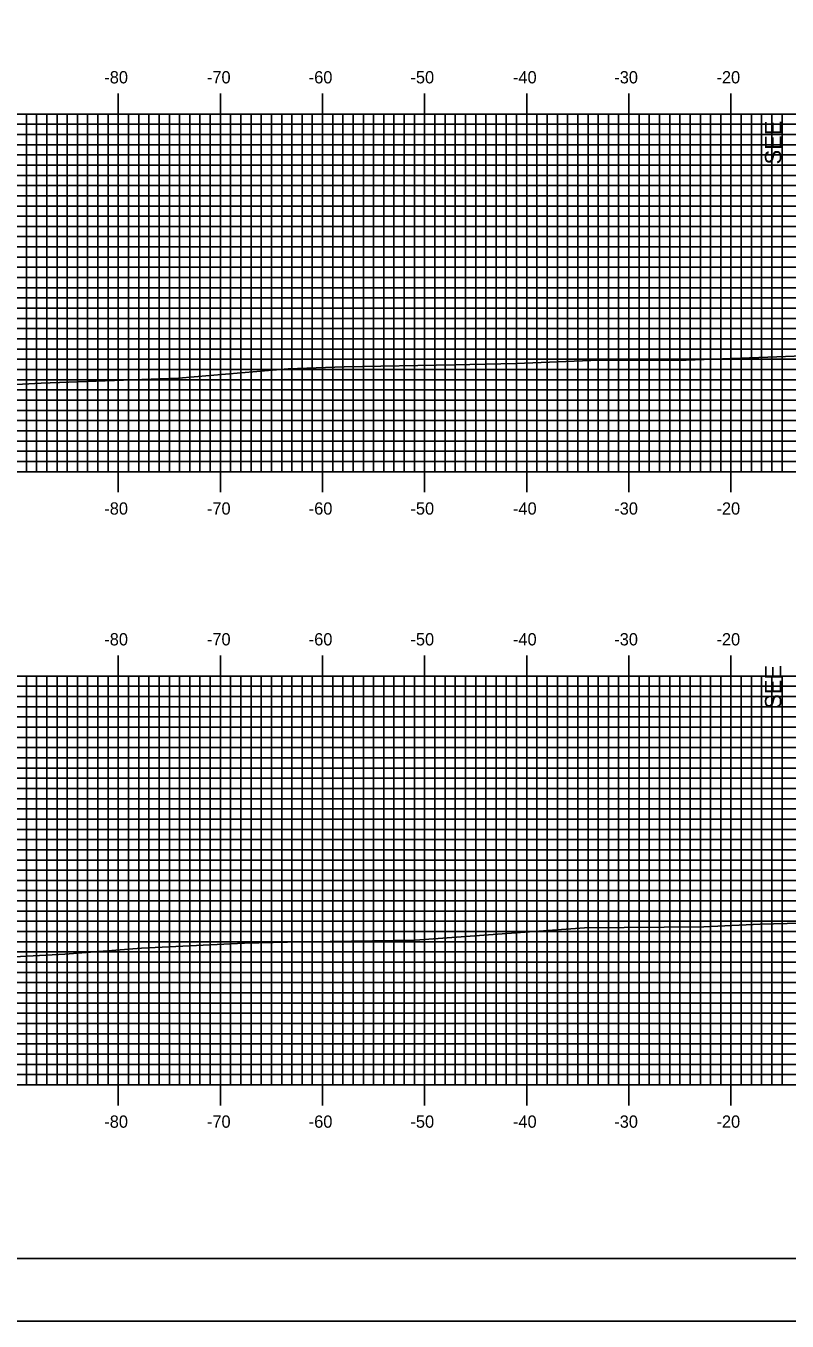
# Model space of a CAD drawing. Extents: x 879 to 1222, y -1658 to -1438.
# Drawn here: x 955.6 to 1030.1, y -1657.7 to -1531 of the extents above; entities that cross this region are included whole.
import ezdxf

# ---------------------------------------------------------------- set-up
doc = ezdxf.new("R2010")
doc.units = 0
for name, color, linetype in [('ANNOTATION', 7, 'Continuous'), ('BORDER', 7, 'Continuous'), ('H_V ANNOTATION', 7, 'Continuous'), ('MAJOR', 7, 'Continuous'), ('MINOR', 7, 'Continuous'), ('PLOT BOUNDARY', 7, 'Continuous'), ('S_Roadway_Centerline', 7, 'Continuous')]:
    doc.layers.add(name, color=color, linetype=linetype)

msp = doc.modelspace()

# ---------------------------------------------------------------- linework, layer by layer
at = {"layer": 'BORDER'}
msp.add_lwpolyline([(895.05, -1651.6), (1215.05, -1651.6), (1215.05, -1441.6), (895.05, -1441.6)], close=True, dxfattribs=at)
at = {"layer": 'MAJOR'}
for p, q in [((964.65, -1537.6), (964.65, -1539.6)), ((974.65, -1537.6), (974.65, -1539.6)), ((984.65, -1537.6), (984.65, -1539.6)), ((994.65, -1537.6), (994.65, -1539.6)), ((1004.65, -1537.6), (1004.65, -1539.6)), ((1014.65, -1537.6), (1014.65, -1539.6)), ((1024.65, -1537.6), (1024.65, -1539.6)), ((904.65, -1539.6), (1184.65, -1539.6)), ((904.65, -1539.6), (1184.65, -1539.6)), ((964.65, -1574.6), (964.65, -1539.6)), ((974.65, -1574.6), (974.65, -1539.6)), ((984.65, -1574.6), (984.65, -1539.6)), ((994.65, -1574.6), (994.65, -1539.6)), ((1004.65, -1574.6), (1004.65, -1539.6)), ((1014.65, -1574.6), (1014.65, -1539.6)), ((1024.65, -1574.6), (1024.65, -1539.6)), ((904.65, -1544.6), (1184.65, -1544.6)), ((904.65, -1549.6), (1184.65, -1549.6)), ((904.65, -1554.6), (1184.65, -1554.6)), ((904.65, -1559.6), (1184.65, -1559.6)), ((904.65, -1564.6), (1184.65, -1564.6)), ((904.65, -1569.6), (1184.65, -1569.6)), ((904.65, -1574.6), (1184.65, -1574.6)), ((904.65, -1574.6), (1184.65, -1574.6)), ((964.65, -1576.61), (964.65, -1574.6)), ((974.65, -1576.61), (974.65, -1574.6)), ((984.65, -1576.61), (984.65, -1574.6)), ((994.65, -1576.61), (994.65, -1574.6)), ((1004.65, -1576.61), (1004.65, -1574.6)), ((1014.65, -1576.61), (1014.65, -1574.6)), ((1024.65, -1576.61), (1024.65, -1574.6)), ((964.65, -1592.6), (964.65, -1594.6)), ((974.65, -1592.6), (974.65, -1594.6)), ((984.65, -1592.6), (984.65, -1594.6)), ((994.65, -1592.6), (994.65, -1594.6)), ((1004.65, -1592.6), (1004.65, -1594.6)), ((1014.65, -1592.6), (1014.65, -1594.6)), ((1024.65, -1592.6), (1024.65, -1594.6)), ((904.65, -1594.6), (1184.65, -1594.6)), ((904.65, -1594.6), (1184.65, -1594.6)), ((964.65, -1634.6), (964.65, -1594.6)), ((974.65, -1634.6), (974.65, -1594.6)), ((984.65, -1634.6), (984.65, -1594.6)), ((994.65, -1634.6), (994.65, -1594.6)), ((1004.65, -1634.6), (1004.65, -1594.6)), ((1014.65, -1634.6), (1014.65, -1594.6)), ((1024.65, -1634.6), (1024.65, -1594.6)), ((904.65, -1599.6), (1184.65, -1599.6)), ((904.65, -1604.6), (1184.65, -1604.6)), ((904.65, -1609.6), (1184.65, -1609.6)), ((904.65, -1614.6), (1184.65, -1614.6)), ((904.65, -1619.6), (1184.65, -1619.6)), ((904.65, -1624.6), (1184.65, -1624.6)), ((904.65, -1629.6), (1184.65, -1629.6)), ((904.65, -1634.6), (1184.65, -1634.6)), ((904.65, -1634.6), (1184.65, -1634.6)), ((964.65, -1636.61), (964.65, -1634.6)), ((974.65, -1636.61), (974.65, -1634.6)), ((984.65, -1636.61), (984.65, -1634.6)), ((994.65, -1636.61), (994.65, -1634.6)), ((1004.65, -1636.61), (1004.65, -1634.6)), ((1014.65, -1636.61), (1014.65, -1634.6)), ((1024.65, -1636.61), (1024.65, -1634.6))]:
    msp.add_line(p, q, dxfattribs=at)
at = {"layer": 'MINOR'}
for p, q in [((955.65, -1574.6), (955.65, -1539.6)), ((956.65, -1574.6), (956.65, -1539.6)), ((957.65, -1574.6), (957.65, -1539.6)), ((958.65, -1574.6), (958.65, -1539.6)), ((959.65, -1574.6), (959.65, -1539.6)), ((960.65, -1574.6), (960.65, -1539.6)), ((961.65, -1574.6), (961.65, -1539.6)), ((962.65, -1574.6), (962.65, -1539.6)), ((963.65, -1574.6), (963.65, -1539.6)), ((965.65, -1574.6), (965.65, -1539.6)), ((966.65, -1574.6), (966.65, -1539.6)), ((967.65, -1574.6), (967.65, -1539.6)), ((968.65, -1574.6), (968.65, -1539.6)), ((969.65, -1574.6), (969.65, -1539.6)), ((970.65, -1574.6), (970.65, -1539.6)), ((971.65, -1574.6), (971.65, -1539.6)), ((972.65, -1574.6), (972.65, -1539.6)), ((973.65, -1574.6), (973.65, -1539.6)), ((975.65, -1574.6), (975.65, -1539.6)), ((976.65, -1574.6), (976.65, -1539.6)), ((977.65, -1574.6), (977.65, -1539.6)), ((978.65, -1574.6), (978.65, -1539.6)), ((979.65, -1574.6), (979.65, -1539.6)), ((980.65, -1574.6), (980.65, -1539.6)), ((981.65, -1574.6), (981.65, -1539.6)), ((982.65, -1574.6), (982.65, -1539.6)), ((983.65, -1574.6), (983.65, -1539.6)), ((985.65, -1574.6), (985.65, -1539.6)), ((986.65, -1574.6), (986.65, -1539.6)), ((987.65, -1574.6), (987.65, -1539.6)), ((988.65, -1574.6), (988.65, -1539.6)), ((989.65, -1574.6), (989.65, -1539.6)), ((990.65, -1574.6), (990.65, -1539.6)), ((991.65, -1574.6), (991.65, -1539.6)), ((992.65, -1574.6), (992.65, -1539.6)), ((993.65, -1574.6), (993.65, -1539.6)), ((995.65, -1574.6), (995.65, -1539.6)), ((996.65, -1574.6), (996.65, -1539.6)), ((997.65, -1574.6), (997.65, -1539.6)), ((998.65, -1574.6), (998.65, -1539.6)), ((999.65, -1574.6), (999.65, -1539.6)), ((1000.65, -1574.6), (1000.65, -1539.6)), ((1001.65, -1574.6), (1001.65, -1539.6)), ((1002.65, -1574.6), (1002.65, -1539.6)), ((1003.65, -1574.6), (1003.65, -1539.6)), ((1005.65, -1574.6), (1005.65, -1539.6)), ((1006.65, -1574.6), (1006.65, -1539.6)), ((1007.65, -1574.6), (1007.65, -1539.6)), ((1008.65, -1574.6), (1008.65, -1539.6)), ((1009.65, -1574.6), (1009.65, -1539.6)), ((1010.65, -1574.6), (1010.65, -1539.6)), ((1011.65, -1574.6), (1011.65, -1539.6)), ((1012.65, -1574.6), (1012.65, -1539.6)), ((1013.65, -1574.6), (1013.65, -1539.6)), ((1015.65, -1574.6), (1015.65, -1539.6)), ((1016.65, -1574.6), (1016.65, -1539.6)), ((1017.65, -1574.6), (1017.65, -1539.6)), ((1018.65, -1574.6), (1018.65, -1539.6)), ((1019.65, -1574.6), (1019.65, -1539.6)), ((1020.65, -1574.6), (1020.65, -1539.6)), ((1021.65, -1574.6), (1021.65, -1539.6)), ((1022.65, -1574.6), (1022.65, -1539.6)), ((1023.65, -1574.6), (1023.65, -1539.6)), ((1025.65, -1574.6), (1025.65, -1539.6)), ((1026.65, -1574.6), (1026.65, -1539.6)), ((1027.65, -1574.6), (1027.65, -1539.6)), ((1028.65, -1574.6), (1028.65, -1539.6)), ((1029.65, -1574.6), (1029.65, -1539.6)), ((904.65, -1540.6), (1184.65, -1540.6)), ((904.65, -1541.6), (1184.65, -1541.6)), ((904.65, -1542.6), (1184.65, -1542.6)), ((904.65, -1543.6), (1184.65, -1543.6)), ((904.65, -1545.6), (1184.65, -1545.6)), ((904.65, -1546.6), (1184.65, -1546.6)), ((904.65, -1547.6), (1184.65, -1547.6)), ((904.65, -1548.6), (1184.65, -1548.6)), ((904.65, -1550.6), (1184.65, -1550.6)), ((904.65, -1551.6), (1184.65, -1551.6)), ((904.65, -1552.6), (1184.65, -1552.6)), ((904.65, -1553.6), (1184.65, -1553.6)), ((904.65, -1555.6), (1184.65, -1555.6)), ((904.65, -1556.6), (1184.65, -1556.6)), ((904.65, -1557.6), (1184.65, -1557.6)), ((904.65, -1558.6), (1184.65, -1558.6)), ((904.65, -1560.6), (1184.65, -1560.6)), ((904.65, -1561.6), (1184.65, -1561.6)), ((904.65, -1562.6), (1184.65, -1562.6)), ((904.65, -1563.6), (1184.65, -1563.6)), ((904.65, -1565.6), (1184.65, -1565.6)), ((904.65, -1566.6), (1184.65, -1566.6)), ((904.65, -1567.6), (1184.65, -1567.6)), ((904.65, -1568.6), (1184.65, -1568.6)), ((904.65, -1570.6), (1184.65, -1570.6)), ((904.65, -1571.6), (1184.65, -1571.6)), ((904.65, -1572.6), (1184.65, -1572.6)), ((904.65, -1573.6), (1184.65, -1573.6)), ((904.65, -1595.6), (1184.65, -1595.6)), ((955.65, -1634.6), (955.65, -1594.6)), ((956.65, -1634.6), (956.65, -1594.6)), ((957.65, -1634.6), (957.65, -1594.6)), ((958.65, -1634.6), (958.65, -1594.6)), ((959.65, -1634.6), (959.65, -1594.6)), ((960.65, -1634.6), (960.65, -1594.6)), ((961.65, -1634.6), (961.65, -1594.6)), ((962.65, -1634.6), (962.65, -1594.6)), ((963.65, -1634.6), (963.65, -1594.6)), ((965.65, -1634.6), (965.65, -1594.6)), ((966.65, -1634.6), (966.65, -1594.6)), ((967.65, -1634.6), (967.65, -1594.6)), ((968.65, -1634.6), (968.65, -1594.6)), ((969.65, -1634.6), (969.65, -1594.6)), ((970.65, -1634.6), (970.65, -1594.6)), ((971.65, -1634.6), (971.65, -1594.6)), ((972.65, -1634.6), (972.65, -1594.6)), ((973.65, -1634.6), (973.65, -1594.6)), ((975.65, -1634.6), (975.65, -1594.6)), ((976.65, -1634.6), (976.65, -1594.6)), ((977.65, -1634.6), (977.65, -1594.6)), ((978.65, -1634.6), (978.65, -1594.6)), ((979.65, -1634.6), (979.65, -1594.6)), ((980.65, -1634.6), (980.65, -1594.6)), ((981.65, -1634.6), (981.65, -1594.6)), ((982.65, -1634.6), (982.65, -1594.6)), ((983.65, -1634.6), (983.65, -1594.6)), ((985.65, -1634.6), (985.65, -1594.6)), ((986.65, -1634.6), (986.65, -1594.6)), ((987.65, -1634.6), (987.65, -1594.6)), ((988.65, -1634.6), (988.65, -1594.6)), ((989.65, -1634.6), (989.65, -1594.6)), ((990.65, -1634.6), (990.65, -1594.6)), ((991.65, -1634.6), (991.65, -1594.6)), ((992.65, -1634.6), (992.65, -1594.6)), ((993.65, -1634.6), (993.65, -1594.6)), ((995.65, -1634.6), (995.65, -1594.6)), ((996.65, -1634.6), (996.65, -1594.6)), ((997.65, -1634.6), (997.65, -1594.6)), ((998.65, -1634.6), (998.65, -1594.6)), ((999.65, -1634.6), (999.65, -1594.6)), ((1000.65, -1634.6), (1000.65, -1594.6)), ((1001.65, -1634.6), (1001.65, -1594.6)), ((1002.65, -1634.6), (1002.65, -1594.6)), ((1003.65, -1634.6), (1003.65, -1594.6)), ((1005.65, -1634.6), (1005.65, -1594.6)), ((1006.65, -1634.6), (1006.65, -1594.6)), ((1007.65, -1634.6), (1007.65, -1594.6)), ((1008.65, -1634.6), (1008.65, -1594.6)), ((1009.65, -1634.6), (1009.65, -1594.6)), ((1010.65, -1634.6), (1010.65, -1594.6)), ((1011.65, -1634.6), (1011.65, -1594.6)), ((1012.65, -1634.6), (1012.65, -1594.6)), ((1013.65, -1634.6), (1013.65, -1594.6)), ((1015.65, -1634.6), (1015.65, -1594.6)), ((1016.65, -1634.6), (1016.65, -1594.6)), ((1017.65, -1634.6), (1017.65, -1594.6)), ((1018.65, -1634.6), (1018.65, -1594.6)), ((1019.65, -1634.6), (1019.65, -1594.6)), ((1020.65, -1634.6), (1020.65, -1594.6)), ((1021.65, -1634.6), (1021.65, -1594.6)), ((1022.65, -1634.6), (1022.65, -1594.6)), ((1023.65, -1634.6), (1023.65, -1594.6)), ((1025.65, -1634.6), (1025.65, -1594.6)), ((1026.65, -1634.6), (1026.65, -1594.6)), ((1027.65, -1634.6), (1027.65, -1594.6)), ((1028.65, -1634.6), (1028.65, -1594.6)), ((1029.65, -1634.6), (1029.65, -1594.6)), ((904.65, -1596.6), (1184.65, -1596.6)), ((904.65, -1597.6), (1184.65, -1597.6)), ((904.65, -1598.6), (1184.65, -1598.6)), ((904.65, -1600.6), (1184.65, -1600.6)), ((904.65, -1601.6), (1184.65, -1601.6)), ((904.65, -1602.6), (1184.65, -1602.6)), ((904.65, -1603.6), (1184.65, -1603.6)), ((904.65, -1605.6), (1184.65, -1605.6)), ((904.65, -1606.6), (1184.65, -1606.6)), ((904.65, -1607.6), (1184.65, -1607.6)), ((904.65, -1608.6), (1184.65, -1608.6)), ((904.65, -1610.6), (1184.65, -1610.6)), ((904.65, -1611.6), (1184.65, -1611.6)), ((904.65, -1612.6), (1184.65, -1612.6)), ((904.65, -1613.6), (1184.65, -1613.6)), ((904.65, -1615.6), (1184.65, -1615.6)), ((904.65, -1616.6), (1184.65, -1616.6)), ((904.65, -1617.6), (1184.65, -1617.6)), ((904.65, -1618.6), (1184.65, -1618.6)), ((904.65, -1620.6), (1184.65, -1620.6)), ((904.65, -1621.6), (1184.65, -1621.6)), ((904.65, -1622.6), (1184.65, -1622.6)), ((904.65, -1623.6), (1184.65, -1623.6)), ((904.65, -1625.6), (1184.65, -1625.6)), ((904.65, -1626.6), (1184.65, -1626.6)), ((904.65, -1627.6), (1184.65, -1627.6)), ((904.65, -1628.6), (1184.65, -1628.6)), ((904.65, -1630.6), (1184.65, -1630.6)), ((904.65, -1631.6), (1184.65, -1631.6)), ((904.65, -1632.6), (1184.65, -1632.6)), ((904.65, -1633.6), (1184.65, -1633.6))]:
    msp.add_line(p, q, dxfattribs=at)
at = {"layer": 'PLOT BOUNDARY'}
msp.add_lwpolyline([(878.86, -1657.72), (1218.86, -1657.72), (1218.86, -1437.72), (878.86, -1437.72)], close=True, dxfattribs=at)
at = {"layer": 'S_Roadway_Centerline'}
for points in [[(904.65, -1569.39), (906.57, -1569.27), (920.82, -1568), (927.72, -1567.6), (937.47, -1567.07), (938.95, -1567), (940.37, -1566.88), (954.06, -1566.11), (957.1, -1565.94), (970.54, -1565.45), (981.3, -1564.54), (986.76, -1564.33), (997.58, -1564.13), (1003.63, -1564.01), (1010.92, -1563.72), (1020.27, -1563.67), (1029.13, -1563.37), (1035.94, -1563.09)], [(904.65, -1624.72), (905.67, -1624.65), (909.42, -1624.47), (921.92, -1623.77), (925.24, -1623.6), (926.03, -1623.57), (939.03, -1623.13), (942.41, -1622.85), (952.55, -1622.18), (959.41, -1621.83), (966.93, -1621.24), (977.01, -1620.75), (981.23, -1620.64), (993.73, -1620.44), (997.78, -1620.14), (1010.31, -1619.24), (1022, -1619.15), (1027.5, -1618.88), (1036.74, -1618.64)]]:
    msp.add_lwpolyline(points, dxfattribs=at)

# ---------------------------------------------------------------- texts
at = {"layer": 'ANNOTATION'}
for p in [(1029.58, -1544.53), (1029.58, -1597.8)]:
    msp.add_text('SEE', height=1.6, rotation=90, dxfattribs=at).set_placement(p)
at = {"layer": 'H_V ANNOTATION'}
for s, p in [('-80', (963.28, -1536.6)), ('-70', (973.33, -1536.6)), ('-60', (983.3, -1536.6)), ('-50', (993.26, -1536.6)), ('-40', (1003.3, -1536.6)), ('-30', (1013.22, -1536.6)), ('-20', (1023.23, -1536.6)), ('-80', (963.28, -1578.8)), ('-70', (973.33, -1578.8)), ('-60', (983.3, -1578.8)), ('-50', (993.26, -1578.8)), ('-40', (1003.3, -1578.8)), ('-30', (1013.22, -1578.8)), ('-20', (1023.23, -1578.8)), ('-80', (963.28, -1591.6)), ('-70', (973.33, -1591.6)), ('-60', (983.3, -1591.6)), ('-50', (993.26, -1591.6)), ('-40', (1003.3, -1591.6)), ('-30', (1013.22, -1591.6)), ('-20', (1023.23, -1591.6)), ('-80', (963.28, -1638.8)), ('-70', (973.33, -1638.8)), ('-60', (983.3, -1638.8)), ('-50', (993.26, -1638.8)), ('-40', (1003.3, -1638.8)), ('-30', (1013.22, -1638.8)), ('-20', (1023.23, -1638.8))]:
    msp.add_text(s, height=1.2, dxfattribs=at).set_placement(p)

doc.saveas('drawing.dxf')
